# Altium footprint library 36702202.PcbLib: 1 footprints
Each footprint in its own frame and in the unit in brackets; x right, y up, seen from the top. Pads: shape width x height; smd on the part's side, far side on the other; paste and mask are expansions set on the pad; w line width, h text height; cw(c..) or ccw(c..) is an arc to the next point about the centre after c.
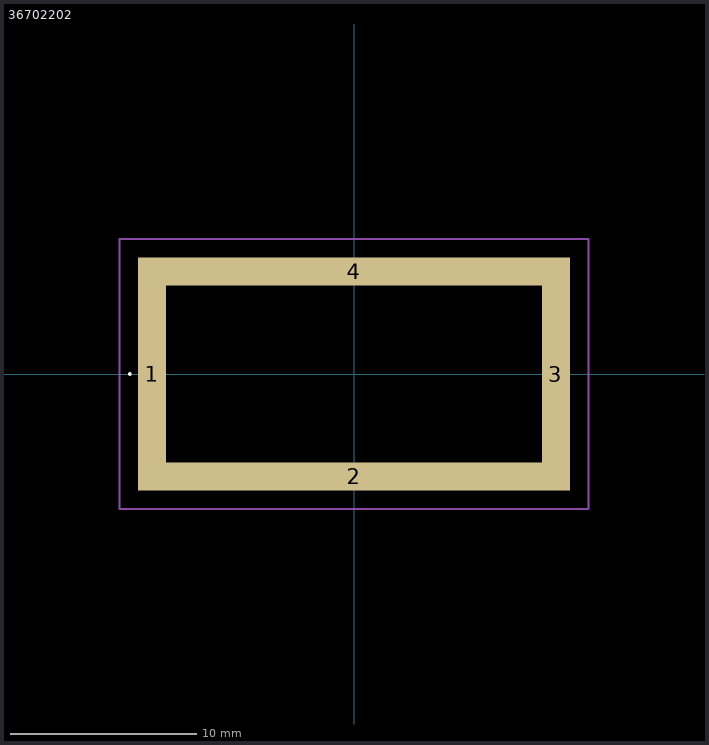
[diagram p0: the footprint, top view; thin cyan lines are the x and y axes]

## 36702202 [mm]
pads (4):
  rect 1.5x9.5 smd: 1(-10.85,0) 3(10.85,0)
  rect 23.2x1.5 smd: 2(0,-5.5) 4(0,5.5)
Top Overlay:
  lines w0.1: -12.1,0 cw(c-12.05,0) -12,0 ; -12.1,0 -12.1,0 ; -12.1,0 ccw(c-12.05,0) -12,0 ; -12,0 -12,0
Mechanical 15:
  lines w0.1: -11,-5.65 11,-5.65 11,5.65 -11,5.65 -11,-5.65
Mechanical 20:
  lines w0.1: -12.6,-7.25 12.6,-7.25 12.6,7.25 -12.6,7.25 -12.6,-7.25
